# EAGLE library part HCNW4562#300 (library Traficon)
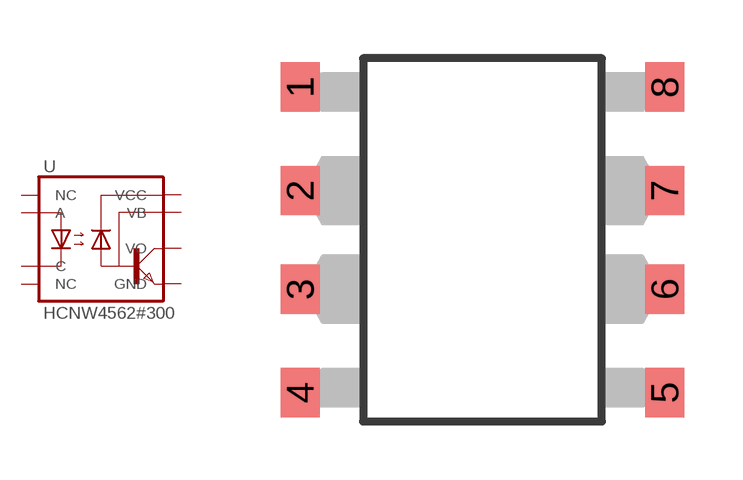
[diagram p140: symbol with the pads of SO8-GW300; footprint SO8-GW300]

Designator prefix U

## HCNW4562#300  [SO8-GW300]
1  NC  nc
2  A  pas
3  C  pas
4  NC  nc
5  GND  pwr
6  VO  pas
7  VB  in
8  VCC  pwr

## Footprint SO8-GW300 (pad centres in mm)
HCPL-772X Package witch Gull Wing Surface Mount Option 300 Source: HCPL7221.pdf
smd 1 x 1.27: 1 -4.69,3.937; 2 -4.69,1.27; 3 -4.69,-1.27; 4 -4.69,-3.937; 5 4.69,-3.937; 6 4.69,-1.27; 7 4.69,1.27; 8 4.69,3.937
